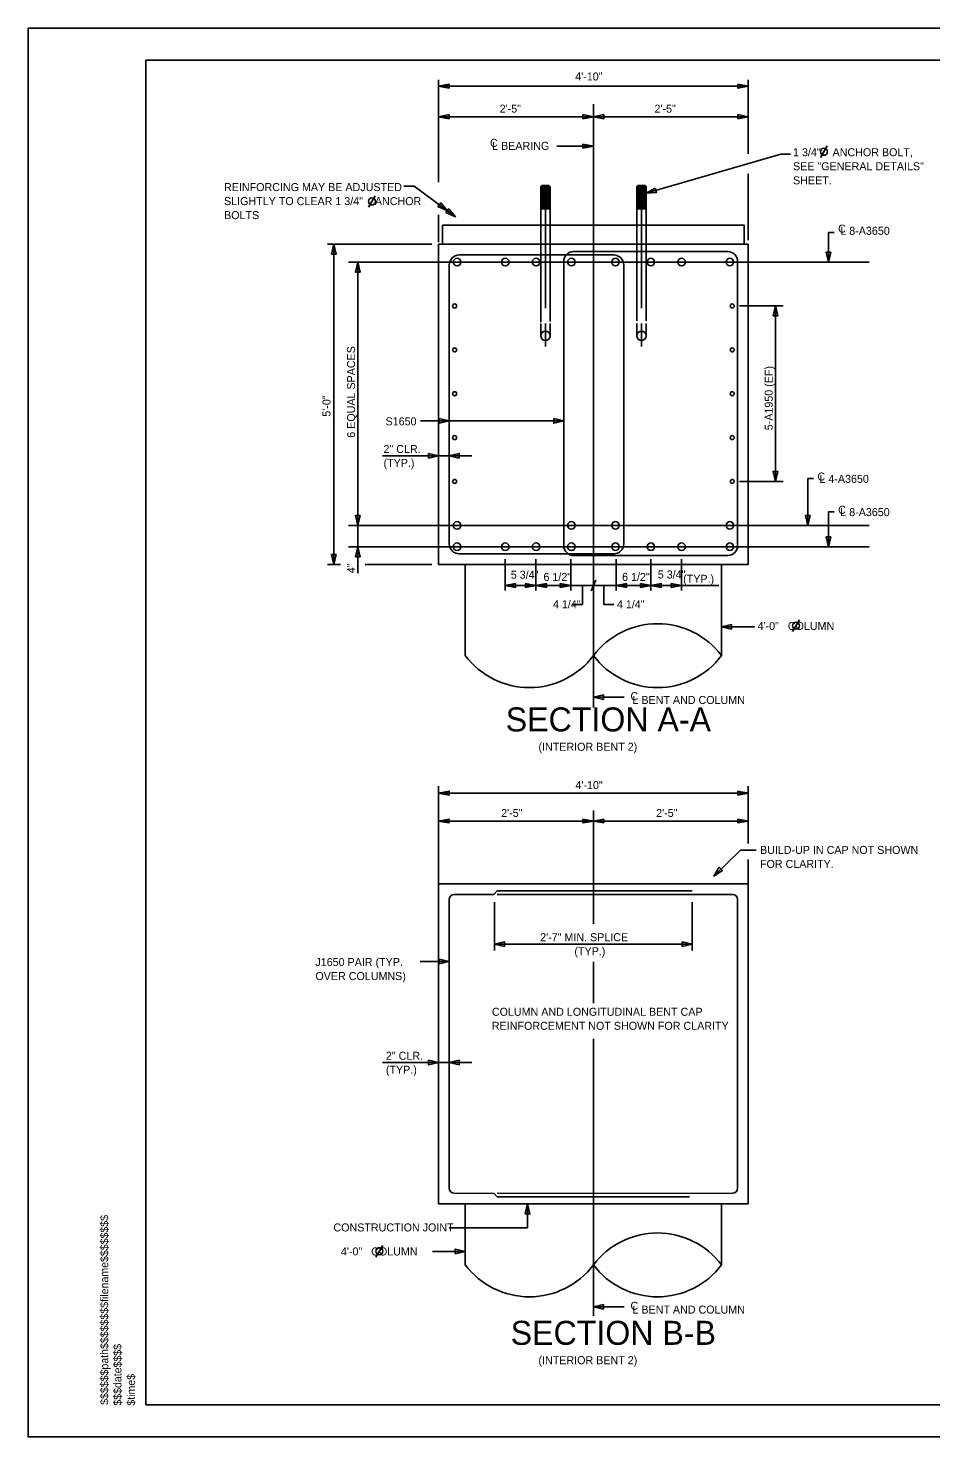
# Model space of a CAD drawing. Extents: x 1970675.2 to 1970711.3, y 796145.2 to 796167.2.
# Drawn here: x 1970675.24 to 1970689.32, y 796145.25 to 796167.25 of the extents above; entities that cross this region are included whole.
import ezdxf

# ---------------------------------------------------------------- set-up
doc = ezdxf.new("R2010")
doc.units = 0
for name, color, linetype in [('BR_AUTO DIMENSION', 7, 'Continuous'), ('BR_BORDER LINES', 7, 'Continuous'), ('BR_CENTER LINES', 7, 'Continuous'), ('BR_CONCRETE', 7, 'Continuous'), ('BR_REBAR', 7, 'Continuous'), ('BR_STRUCTURAL STEEL', 7, 'Continuous'), ('BR_TEXT', 7, 'Continuous'), ('Level 31', 7, 'Continuous'), ('RD_SHT_ID', 7, 'Continuous')]:
    doc.layers.add(name, color=color, linetype=linetype)

msp = doc.modelspace()

# ---------------------------------------------------------------- linework, layer by layer
at = {"layer": 'BR_AUTO DIMENSION'}
for p, q in [((1970681.641, 796164.84), (1970681.641, 796166.442)), ((1970681.641, 796166.34), (1970686.474, 796166.34)), ((1970686.474, 796165.282), (1970686.474, 796166.442)), ((1970684.058, 796165.691), (1970684.058, 796166.059)), ((1970681.641, 796165.864), (1970684.058, 796165.864)), ((1970686.474, 796165.864), (1970684.058, 796165.864)), ((1970683.488, 796165.404), (1970684.058, 796165.404)), ((1970684.881, 796164.669), (1970686.981, 796165.279)), ((1970686.981, 796165.279), (1970687.135, 796165.279)), ((1970686.474, 796163.933), (1970686.474, 796164.969)), ((1970681.641, 796163.904), (1970681.641, 796164.33)), ((1970681.537, 796163.871), (1970679.908, 796163.871)), ((1970680.006, 796163.871), (1970680.006, 796158.871)), ((1970680.381, 796163.593), (1970680.381, 796158.734)), ((1970687.021, 796162.908), (1970686.339, 796162.908)), ((1970686.898, 796162.908), (1970686.898, 796160.167)), ((1970683.595, 796161.112), (1970681.361, 796161.112)), ((1970682.159, 796160.568), (1970680.767, 796160.568)), ((1970687.021, 796160.167), (1970686.339, 796160.167)), ((1970680.113, 796158.871), (1970679.908, 796158.871)), ((1970681.537, 796158.871), (1970680.496, 796158.871)), ((1970682.682, 796158.462), (1970682.682, 796158.956)), ((1970683.161, 796158.462), (1970683.161, 796158.956)), ((1970683.704, 796158.462), (1970683.704, 796158.956)), ((1970684.412, 796158.462), (1970684.412, 796158.956)), ((1970684.955, 796158.462), (1970684.955, 796158.956)), ((1970685.434, 796158.462), (1970685.434, 796158.956)), ((1970684.021, 796158.459), (1970684.095, 796158.624)), ((1970686.013, 796158.542), (1970682.698, 796158.542)), ((1970683.888, 796158.243), (1970683.888, 796158.542)), ((1970684.221, 796158.243), (1970684.221, 796158.542)), ((1970683.732, 796158.243), (1970683.888, 796158.243)), ((1970684.378, 796158.243), (1970684.221, 796158.243)), ((1970686.058, 796157.896), (1970686.57, 796157.896)), ((1970684.058, 796156.797), (1970684.54, 796156.797)), ((1970681.641, 796153.696), (1970681.641, 796155.409)), ((1970681.641, 796155.301), (1970686.475, 796155.301)), ((1970686.475, 796154.515), (1970686.475, 796155.409)), ((1970681.641, 796154.864), (1970684.058, 796154.864)), ((1970686.475, 796154.864), (1970684.058, 796154.864)), ((1970686.475, 796153.65), (1970686.475, 796154.264)), ((1970682.516, 796153.596), (1970682.516, 796152.842)), ((1970685.599, 796153.596), (1970685.599, 796152.842)), ((1970682.516, 796152.94), (1970685.599, 796152.94)), ((1970681.808, 796152.668), (1970681.354, 796152.668)), ((1970682.159, 796151.091), (1970680.766, 796151.091)), ((1970683.031, 796148.883), (1970683.031, 796148.51)), ((1970683.031, 796148.51), (1970681.807, 796148.51)), ((1970682.058, 796148.142), (1970681.546, 796148.142)), ((1970684.058, 796147.276), (1970684.54, 796147.276))]:
    msp.add_line(p, q, dxfattribs=at)
for points in [[(1970681.804, 796166.309), (1970681.641, 796166.34), (1970681.804, 796166.371)], [(1970686.312, 796166.371), (1970686.474, 796166.34), (1970686.312, 796166.309)], [(1970681.804, 796165.833), (1970681.641, 796165.864), (1970681.804, 796165.896)], [(1970683.895, 796165.896), (1970684.058, 796165.864), (1970683.895, 796165.833)], [(1970684.22, 796165.833), (1970684.058, 796165.864), (1970684.22, 796165.896)], [(1970686.312, 796165.896), (1970686.474, 796165.864), (1970686.312, 796165.833)], [(1970683.895, 796165.435), (1970684.058, 796165.404), (1970683.895, 796165.373)], [(1970685.021, 796164.747), (1970684.881, 796164.669), (1970685.041, 796164.678)], [(1970681.631, 796164.459), (1970681.778, 796164.394), (1970681.675, 796164.516)], [(1970681.756, 796164.365), (1970681.903, 796164.301), (1970681.799, 796164.423)], [(1970679.97, 796163.715), (1970680.006, 796163.871), (1970680.042, 796163.715)], [(1970687.764, 796163.749), (1970687.728, 796163.593), (1970687.692, 796163.749)], [(1970680.345, 796163.437), (1970680.381, 796163.593), (1970680.417, 796163.437)], [(1970686.862, 796162.752), (1970686.898, 796162.908), (1970686.934, 796162.752)], [(1970681.652, 796161.148), (1970681.808, 796161.112), (1970681.652, 796161.076)], [(1970683.439, 796161.148), (1970683.595, 796161.112), (1970683.439, 796161.076)], [(1970681.485, 796160.604), (1970681.641, 796160.568), (1970681.485, 796160.532)], [(1970681.964, 796160.532), (1970681.808, 796160.568), (1970681.964, 796160.604)], [(1970686.934, 796160.323), (1970686.898, 796160.167), (1970686.862, 796160.323)], [(1970680.417, 796159.637), (1970680.381, 796159.481), (1970680.345, 796159.637)], [(1970687.44, 796159.637), (1970687.404, 796159.481), (1970687.368, 796159.637)], [(1970687.764, 796159.304), (1970687.728, 796159.148), (1970687.692, 796159.304)], [(1970680.042, 796159.027), (1970680.006, 796158.871), (1970679.97, 796159.027)], [(1970680.345, 796158.992), (1970680.381, 796159.148), (1970680.417, 796158.992)], [(1970682.844, 796158.573), (1970682.682, 796158.542), (1970682.844, 796158.511)], [(1970682.998, 796158.511), (1970683.161, 796158.542), (1970682.998, 796158.573)], [(1970683.323, 796158.573), (1970683.161, 796158.542), (1970683.323, 796158.511)], [(1970683.541, 796158.511), (1970683.704, 796158.542), (1970683.541, 796158.573)], [(1970684.574, 796158.511), (1970684.412, 796158.542), (1970684.574, 796158.573)], [(1970684.792, 796158.573), (1970684.955, 796158.542), (1970684.792, 796158.511)], [(1970685.117, 796158.511), (1970684.955, 796158.542), (1970685.117, 796158.573)], [(1970685.271, 796158.573), (1970685.434, 796158.542), (1970685.271, 796158.511)], [(1970686.214, 796157.86), (1970686.058, 796157.896), (1970686.214, 796157.932)], [(1970684.214, 796156.761), (1970684.058, 796156.797), (1970684.214, 796156.833)], [(1970681.804, 796155.27), (1970681.641, 796155.301), (1970681.804, 796155.332)], [(1970686.312, 796155.332), (1970686.475, 796155.301), (1970686.312, 796155.27)], [(1970681.804, 796154.833), (1970681.641, 796154.864), (1970681.804, 796154.895)], [(1970683.895, 796154.895), (1970684.058, 796154.864), (1970683.895, 796154.833)], [(1970684.22, 796154.833), (1970684.058, 796154.864), (1970684.22, 796154.895)], [(1970686.312, 796154.895), (1970686.475, 796154.864), (1970686.312, 796154.833)], [(1970686.019, 796154.141), (1970685.937, 796154.004), (1970686.071, 796154.092)], [(1970682.672, 796152.904), (1970682.516, 796152.94), (1970682.672, 796152.976)], [(1970685.443, 796152.976), (1970685.599, 796152.94), (1970685.443, 796152.904)], [(1970681.652, 796152.704), (1970681.808, 796152.668), (1970681.652, 796152.632)], [(1970681.485, 796151.127), (1970681.641, 796151.091), (1970681.485, 796151.055)], [(1970681.963, 796151.055), (1970681.807, 796151.091), (1970681.963, 796151.127)], [(1970682.995, 796148.727), (1970683.031, 796148.883), (1970683.067, 796148.727)], [(1970681.902, 796148.106), (1970682.058, 796148.142), (1970681.902, 796148.178)], [(1970684.214, 796147.24), (1970684.058, 796147.276), (1970684.214, 796147.312)]]:
    msp.add_lwpolyline(points, close=True, dxfattribs=at)
for points in [[(1970681.903, 796164.301), (1970681.262, 796164.78), (1970681.097, 796164.78)], [(1970687.728, 796163.593), (1970687.728, 796164.056), (1970687.816, 796164.056)], [(1970687.404, 796159.481), (1970687.404, 796160.213), (1970687.491, 796160.213)], [(1970687.728, 796159.148), (1970687.728, 796159.694), (1970687.816, 796159.694)], [(1970685.937, 796154.004), (1970686.351, 796154.408), (1970686.595, 796154.408)]]:
    msp.add_lwpolyline(points, dxfattribs=at)
at = {"layer": 'BR_BORDER LINES'}
for p, q in [((1970710.736, 796166.746), (1970677.07, 796166.746)), ((1970677.07, 796145.746), (1970677.07, 796166.746)), ((1970677.07, 796145.746), (1970710.736, 796145.746))]:
    msp.add_line(p, q, dxfattribs=at)
at = {"layer": 'BR_CENTER LINES'}
for p, q in [((1970684.058, 796165.691), (1970684.058, 796156.638)), ((1970683.308, 796163.871), (1970683.308, 796164.576)), ((1970684.808, 796163.871), (1970684.808, 796164.576)), ((1970683.308, 796162.872), (1970683.308, 796163.871)), ((1970684.808, 796162.872), (1970684.808, 796163.871)), ((1970680.233, 796163.593), (1970688.361, 796163.593)), ((1970683.308, 796162.277), (1970683.308, 796162.634)), ((1970684.808, 796162.277), (1970684.808, 796162.634)), ((1970680.233, 796159.481), (1970688.361, 796159.481)), ((1970680.233, 796159.148), (1970688.361, 796159.148)), ((1970684.058, 796155.026), (1970684.058, 796153.259)), ((1970684.058, 796152.665), (1970684.058, 796152.017)), ((1970684.058, 796151.462), (1970684.058, 796147.135))]:
    msp.add_line(p, q, dxfattribs=at)
at = {"layer": 'BR_CONCRETE'}
for p, q in [((1970681.704, 796163.871), (1970681.704, 796164.172)), ((1970681.704, 796164.172), (1970686.412, 796164.172)), ((1970686.412, 796164.172), (1970686.412, 796163.871)), ((1970681.641, 796163.871), (1970681.641, 796159.037)), ((1970681.641, 796158.871), (1970681.641, 796163.871)), ((1970686.474, 796163.871), (1970681.641, 796163.871)), ((1970686.474, 796163.871), (1970686.474, 796158.871)), ((1970681.641, 796158.871), (1970686.474, 796158.871)), ((1970682.058, 796158.871), (1970682.058, 796158.568)), ((1970686.058, 796158.871), (1970686.058, 796157.446)), ((1970682.058, 796158.568), (1970682.058, 796157.446)), ((1970681.641, 796153.883), (1970681.641, 796149.05)), ((1970681.641, 796148.883), (1970681.641, 796153.883)), ((1970686.474, 796153.883), (1970681.641, 796153.883)), ((1970686.474, 796153.883), (1970686.474, 796148.883)), ((1970681.64, 796148.883), (1970682.058, 796148.883)), ((1970682.058, 796148.883), (1970686.058, 796148.883)), ((1970682.058, 796148.883), (1970682.058, 796147.932)), ((1970686.058, 796148.883), (1970686.474, 796148.883)), ((1970686.058, 796148.883), (1970686.058, 796147.932))]:
    msp.add_line(p, q, dxfattribs=at)
for centre, start, end in [((1970685.058, 796156.693), 37.0023, 142.9977), ((1970683.058, 796158.2), 217.0023, 322.9977), ((1970685.058, 796158.2), 217.0023, 322.9977), ((1970685.058, 796147.178), 37.0023, 142.9977), ((1970683.058, 796148.685), 217.0023, 322.9977), ((1970685.058, 796148.685), 217.0023, 322.9977)]:
    msp.add_arc(centre, 1.252, start, end, dxfattribs=at)
at = {"layer": 'BR_REBAR'}
for p, q in [((1970681.962, 796163.704), (1970684.375, 796163.704)), ((1970686.154, 796163.758), (1970683.751, 796163.758)), ((1970681.808, 796163.55), (1970681.808, 796159.191)), ((1970683.595, 796163.602), (1970683.595, 796159.166)), ((1970684.531, 796163.548), (1970684.531, 796159.193)), ((1970686.308, 796163.605), (1970686.308, 796159.164)), ((1970681.961, 796159.037), (1970684.375, 796159.037)), ((1970686.154, 796159.01), (1970683.751, 796159.01)), ((1970682.502, 796153.717), (1970682.558, 796153.772)), ((1970685.599, 796153.772), (1970682.558, 796153.772)), ((1970681.808, 796153.639), (1970681.807, 796149.128)), ((1970681.886, 796153.717), (1970682.503, 796153.717)), ((1970686.229, 796153.716), (1970682.558, 796153.717)), ((1970686.308, 796153.638), (1970686.308, 796149.378)), ((1970686.307, 796153.388), (1970686.307, 796149.128)), ((1970682.502, 796149.049), (1970681.885, 796149.05)), ((1970682.501, 796149.05), (1970682.557, 796148.994)), ((1970686.229, 796149.049), (1970682.557, 796149.05)), ((1970685.557, 796148.994), (1970682.557, 796148.994))]:
    msp.add_line(p, q, dxfattribs=at)
for centre, radius in [((1970681.929, 796163.593), 0.0588), ((1970682.682, 796163.593), 0.0588), ((1970683.162, 796163.593), 0.0588), ((1970683.714, 796163.593), 0.0588), ((1970684.402, 796163.593), 0.0588), ((1970684.954, 796163.593), 0.0588), ((1970685.434, 796163.593), 0.0588), ((1970686.187, 796163.593), 0.0588), ((1970681.891, 796162.908), 0.0313), ((1970686.224, 796162.908), 0.0313), ((1970681.891, 796162.222), 0.0313), ((1970686.224, 796162.222), 0.0313), ((1970681.891, 796161.537), 0.0313), ((1970686.224, 796161.537), 0.0313), ((1970681.891, 796160.852), 0.0313), ((1970686.224, 796160.852), 0.0313), ((1970681.891, 796160.167), 0.0313), ((1970686.224, 796160.167), 0.0313), ((1970681.929, 796159.481), 0.0588), ((1970683.714, 796159.481), 0.0588), ((1970684.402, 796159.481), 0.0588), ((1970686.187, 796159.481), 0.0588), ((1970681.929, 796159.148), 0.0588), ((1970682.682, 796159.148), 0.0588), ((1970683.162, 796159.148), 0.0588), ((1970683.714, 796159.148), 0.0588), ((1970684.402, 796159.148), 0.0588), ((1970684.954, 796159.148), 0.0588), ((1970685.434, 796159.148), 0.0588), ((1970686.187, 796159.148), 0.0588)]:
    msp.add_circle(centre, radius, dxfattribs=at)
for centre, radius, start, end in [((1970681.964, 796163.548), 0.156, 91.025, 178.975), ((1970683.751, 796163.602), 0.156, 90, 180), ((1970684.375, 796163.548), 0.156, 0, 90), ((1970686.152, 796163.602), 0.156, 1.025, 88.975), ((1970681.964, 796159.193), 0.156, 181.025, 268.975), ((1970683.751, 796159.166), 0.156, 180, 270), ((1970684.375, 796159.193), 0.156, 270, 0), ((1970686.152, 796159.166), 0.156, 271.025, 358.975), ((1970681.886, 796153.639), 0.0781, 90, 180), ((1970686.23, 796153.638), 0.0781, 360, 90), ((1970681.885, 796149.128), 0.0781, 180, 270), ((1970686.229, 796149.128), 0.0781, 270, 360)]:
    msp.add_arc(centre, radius, start, end, dxfattribs=at)
at = {"layer": 'BR_STRUCTURAL STEEL'}
for p, q in [((1970683.253, 796164.787), (1970683.235, 796164.769)), ((1970683.381, 796164.769), (1970683.235, 796164.769)), ((1970683.235, 796164.769), (1970683.235, 796163.871)), ((1970683.381, 796164.751), (1970683.235, 796164.751)), ((1970683.381, 796164.733), (1970683.235, 796164.733)), ((1970683.363, 796164.787), (1970683.253, 796164.787)), ((1970683.381, 796164.769), (1970683.363, 796164.787)), ((1970683.381, 796164.769), (1970683.381, 796163.871)), ((1970684.753, 796164.787), (1970684.735, 796164.769)), ((1970684.881, 796164.769), (1970684.735, 796164.769)), ((1970684.735, 796164.769), (1970684.735, 796163.871)), ((1970684.881, 796164.751), (1970684.735, 796164.751)), ((1970684.881, 796164.733), (1970684.735, 796164.733)), ((1970684.863, 796164.787), (1970684.753, 796164.787)), ((1970684.881, 796164.769), (1970684.863, 796164.787)), ((1970684.881, 796164.769), (1970684.881, 796163.871)), ((1970683.381, 796164.715), (1970683.235, 796164.715)), ((1970683.381, 796164.696), (1970683.235, 796164.696)), ((1970683.381, 796164.678), (1970683.235, 796164.678)), ((1970683.381, 796164.66), (1970683.235, 796164.66)), ((1970683.381, 796164.642), (1970683.235, 796164.642)), ((1970683.381, 796164.623), (1970683.235, 796164.623)), ((1970683.381, 796164.605), (1970683.235, 796164.605)), ((1970683.381, 796164.587), (1970683.235, 796164.587)), ((1970683.381, 796164.569), (1970683.235, 796164.569)), ((1970683.381, 796164.551), (1970683.235, 796164.551)), ((1970683.381, 796164.532), (1970683.235, 796164.532)), ((1970683.381, 796164.514), (1970683.235, 796164.514)), ((1970684.881, 796164.715), (1970684.735, 796164.715)), ((1970684.881, 796164.696), (1970684.735, 796164.696)), ((1970684.881, 796164.678), (1970684.735, 796164.678)), ((1970684.881, 796164.66), (1970684.735, 796164.66)), ((1970684.881, 796164.642), (1970684.735, 796164.642)), ((1970684.881, 796164.623), (1970684.735, 796164.623)), ((1970684.881, 796164.605), (1970684.735, 796164.605)), ((1970684.881, 796164.587), (1970684.735, 796164.587)), ((1970684.881, 796164.569), (1970684.735, 796164.569)), ((1970684.881, 796164.551), (1970684.735, 796164.551)), ((1970684.881, 796164.532), (1970684.735, 796164.532)), ((1970684.881, 796164.514), (1970684.735, 796164.514)), ((1970683.381, 796164.496), (1970683.235, 796164.496)), ((1970683.381, 796164.478), (1970683.235, 796164.478)), ((1970683.381, 796164.459), (1970683.235, 796164.459)), ((1970683.381, 796164.441), (1970683.235, 796164.441)), ((1970683.381, 796164.423), (1970683.235, 796164.423)), ((1970684.881, 796164.496), (1970684.735, 796164.496)), ((1970684.881, 796164.478), (1970684.735, 796164.478)), ((1970684.881, 796164.459), (1970684.735, 796164.459)), ((1970684.881, 796164.441), (1970684.735, 796164.441)), ((1970684.881, 796164.423), (1970684.735, 796164.423)), ((1970683.235, 796163.871), (1970683.235, 796162.657)), ((1970683.381, 796163.871), (1970683.381, 796162.664)), ((1970684.735, 796163.871), (1970684.735, 796162.674)), ((1970684.881, 796163.871), (1970684.881, 796162.677)), ((1970683.235, 796162.634), (1970683.235, 796162.443)), ((1970683.381, 796162.634), (1970683.381, 796162.446)), ((1970684.735, 796162.634), (1970684.735, 796162.443)), ((1970684.881, 796162.634), (1970684.881, 796162.446))]:
    msp.add_line(p, q, dxfattribs=at)
for centre in [(1970683.308, 796162.443), (1970684.808, 796162.443)]:
    msp.add_circle(centre, 0.0729, dxfattribs=at)
at = {"layer": 'BR_TEXT'}
for p, q in [((1970687.603, 796165.225), (1970687.708, 796165.407)), ((1970680.549, 796164.449), (1970680.654, 796164.63)), ((1970680.006, 796158.871), (1970680.006, 796159.018)), ((1970687.167, 796157.823), (1970687.272, 796158.005)), ((1970682.558, 796152.94), (1970682.635, 796152.94)), ((1970685.599, 796152.94), (1970685.502, 796152.94)), ((1970680.664, 796148.054), (1970680.769, 796148.236))]:
    msp.add_line(p, q, dxfattribs=at)
for centre in [(1970687.656, 796165.316), (1970680.601, 796164.54), (1970687.22, 796157.914), (1970680.716, 796148.145)]:
    msp.add_circle(centre, 0.055, dxfattribs=at)
at = {"layer": 'Level 31'}
msp.add_line((1970711.236, 796167.246), (1970675.236, 796167.246), dxfattribs=at)
msp.add_lwpolyline([(1970675.236, 796167.246), (1970675.236, 796145.246), (1970711.236, 796145.246), (1970711.236, 796167.246)], dxfattribs=at)

# ---------------------------------------------------------------- texts
at = {"layer": 'BR_AUTO DIMENSION'}
for s, p in [('4\'-10"', (1970683.774, 796166.43)), ('2\'-5"', (1970682.594, 796165.927)), ('2\'-5"', (1970685.011, 796165.927)), ('4\'-10"', (1970683.777, 796155.363)), ('2\'-5"', (1970682.618, 796154.927)), ('2\'-5"', (1970685.037, 796154.927))]:
    msp.add_text(s, height=0.125, dxfattribs=at).set_placement(p)
at = {"layer": 'BR_TEXT'}
for s, height, p in [('C', 0.125, (1970682.444, 796165.393)), ('L BEARING', 0.125, (1970682.477, 796165.346)), ('C', 0.125, (1970687.877, 796164.053)), ('L 8-A3650', 0.125, (1970687.911, 796164.019)), ('S1650', 0.125, (1970680.814, 796161.043)), ('2" CLR.', 0.125, (1970680.782, 796160.612)), ('(TYP.)', 0.125, (1970680.782, 796160.394)), ('6 1/2"', 0.125, (1970683.278, 796158.614)), ('6 1/2"', 0.125, (1970684.505, 796158.614)), ('4 1/4"', 0.125, (1970683.426, 796158.186)), ('4 1/4"', 0.125, (1970684.424, 796158.186)), ('SECTION A-A', 0.375, (1970682.689, 796156.263)), ('SECTION B-B', 0.375, (1970682.766, 796146.683))]:
    msp.add_text(s, height=height, dxfattribs=at).set_placement(p)
for s, rotation, p in [('1 3/4"    ANCHOR BOLT, ', 360, (1970687.173, 796165.246)), ('SEE "GENERAL DETAILS"', 360, (1970687.173, 796165.027)), ('REINFORCING MAY BE ADJUSTED', 360, (1970678.293, 796164.702)), ('SHEET.', 360, (1970687.173, 796164.808)), ('SLIGHTLY TO CLEAR 1 3/4"    ANCHOR', 360, (1970678.293, 796164.483)), ('BOLTS', 360, (1970678.293, 796164.264)), ('6 EQUAL SPACES', 90, (1970680.338, 796160.85)), ('5-A1950 (EF)', 90, (1970686.856, 796160.967)), ('5\'-0"', 90, (1970679.954, 796161.179)), ('C', 360, (1970687.553, 796160.181)), ('L 4-A3650', 360, (1970687.585, 796160.145)), ('C', 360, (1970687.877, 796159.662)), ('L 8-A3650', 360, (1970687.91, 796159.626)), ('4"', 90, (1970680.338, 796158.734)), ('5 3/4"', 360, (1970685.062, 796158.652)), ('5 3/4"', 360, (1970682.768, 796158.648)), ('(TYP.)', 360, (1970685.458, 796158.584)), ('4\'-0"   COLUMN', 360, (1970686.62, 796157.848)), ('C', 360, (1970684.636, 796156.751)), ('L BENT AND COLUMN', 360, (1970684.667, 796156.692)), ('(INTERIOR BENT 2)', 360, (1970683.2, 796155.961)), ('BUILD-UP IN CAP NOT SHOWN', 360, (1970686.657, 796154.35)), ('FOR CLARITY.', 360, (1970686.657, 796154.131)), ('2\'-7" MIN. SPLICE', 360, (1970683.226, 796152.987)), ('(TYP.)', 360, (1970683.761, 796152.768)), ('J1650 PAIR (TYP.', 360, (1970679.719, 796152.599)), ('OVER COLUMNS)', 360, (1970679.719, 796152.38)), ('COLUMN AND LONGITUDINAL BENT CAP', 360, (1970682.473, 796151.822)), ('REINFORCEMENT NOT SHOWN FOR CLARITY', 360, (1970682.473, 796151.603)), ('2" CLR.', 360, (1970680.819, 796151.135)), ('(TYP.)', 360, (1970680.819, 796150.917)), ('CONSTRUCTION JOINT', 360, (1970680, 796148.454)), ('4\'-0"   COLUMN', 360, (1970680.117, 796148.079)), ('C', 360, (1970684.636, 796147.23)), ('L BENT AND COLUMN', 360, (1970684.667, 796147.171)), ('(INTERIOR BENT 2)', 360, (1970683.2, 796146.381))]:
    msp.add_text(s, height=0.125, rotation=rotation, dxfattribs=at).set_placement(p)
at = {"layer": 'RD_SHT_ID'}
for s, height, p in [('$$$$$$path$$$$$$$$filename$$$$$$$$', 0.12347, (1970676.486, 796145.746)), ('$$$date$$$$', 0.12347, (1970676.692, 796145.733)), ('$time$', 0.1235, (1970676.903, 796145.733))]:
    msp.add_text(s, height=height, rotation=90, dxfattribs=at).set_placement(p)

doc.saveas('drawing.dxf')
